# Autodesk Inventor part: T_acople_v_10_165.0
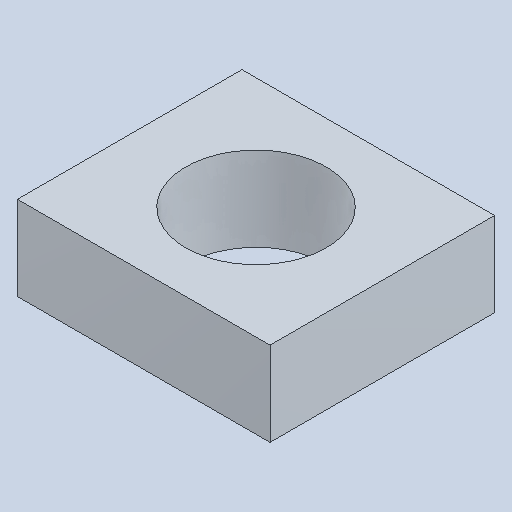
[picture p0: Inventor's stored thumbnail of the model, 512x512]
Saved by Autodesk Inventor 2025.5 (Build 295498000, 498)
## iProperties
Created: 2026-10
Part Number: T_acople_v_10_165.0
Material: Genérico
Document SubType Name: Modeling
Designer: Luis M
Density: 1 g/cm^3
Appearance: Valor por defecto
Author: Luis M
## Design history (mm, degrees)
feature "Base1"
node "Sólido1"
